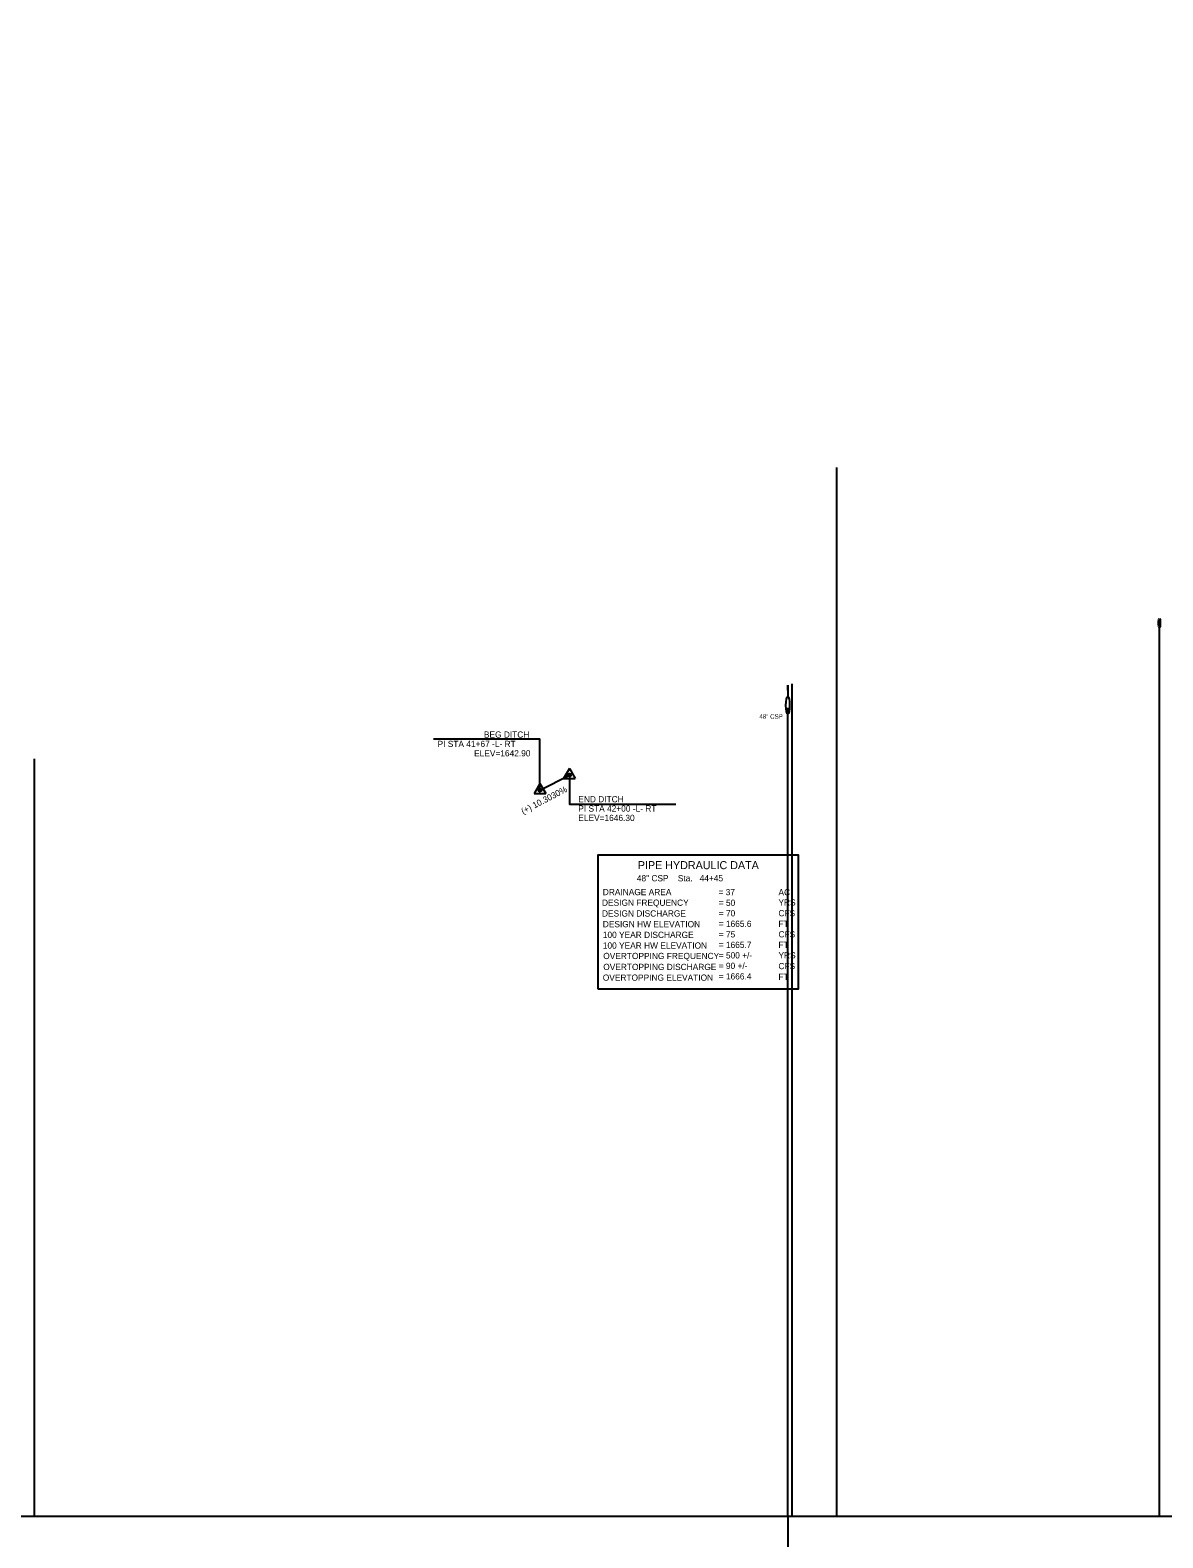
# Model space of a CAD drawing. Extents: x 1025306 to 1036906, y 638983 to 643947.
# Drawn here: x 1027901 to 1029171, y 639865 to 641557 of the extents above; entities that cross this region are included whole.
import ezdxf

# ---------------------------------------------------------------- set-up
doc = ezdxf.new("R2010")
doc.units = 0
for name, color, linetype in [('Default', 7, 'Continuous'), ('Prop PFL Cross Pipe CELL', 7, 'Continuous'), ('Prop PFL Cross Pipe Text CELL', 7, 'Continuous'), ('Prop PFL Pipe Hydraulic Data CELL', 7, 'Continuous'), ('Prop Vertical Profile Ditch Grade Right', 7, 'Continuous'), ('Prop Vertical Profile Ditch Grade Right Label', 7, 'Continuous'), ('Prop VPI Ditch Grade Right Label', 7, 'Continuous'), ('Scratch_Level_0', 7, 'Continuous'), ('Scratch_Level_1', 7, 'Continuous'), ('Scratch_Level_3', 7, 'Continuous')]:
    doc.layers.add(name, color=color, linetype=linetype)

msp = doc.modelspace()

# ---------------------------------------------------------------- linework, layer by layer
at = {"layer": 'Default'}
for p, q in [((1028505.6, 640728.4), (1028499.1, 640717.2)), ((1028505.6, 640728.4), (1028512.1, 640717.2)), ((1028472.6, 640711.4), (1028466.1, 640700.2)), ((1028472.6, 640711.4), (1028479.1, 640700.2)), ((1028499.1, 640717.2), (1028512.1, 640717.2)), ((1028466.1, 640700.2), (1028479.1, 640700.2))]:
    msp.add_line(p, q, dxfattribs=at)
for centre, radius in [((1028505.6, 640720.9), 1.75), ((1028505.6, 640720.9), 1.2), ((1028472.6, 640703.9), 1.75), ((1028472.6, 640703.9), 1.2)]:
    msp.add_circle(centre, radius, dxfattribs=at)
at = {"layer": 'Prop PFL Cross Pipe CELL'}
for centre, major_axis in [((1029167.6, 640891.4), (0, 5)), ((1028750.6, 640799.1), (0, 10))]:
    msp.add_ellipse(centre, major_axis=major_axis, ratio=0.2, dxfattribs=at)
at = {"layer": 'Prop PFL Pipe Hydraulic Data CELL'}
msp.add_lwpolyline([(1028537.6, 640481), (1028762.6, 640481), (1028762.6, 640631), (1028537.6, 640631)], close=True, dxfattribs=at)
at = {"layer": 'Prop Vertical Profile Ditch Grade Right'}
msp.add_line((1028472.6, 640703.9), (1028505.6, 640720.9), dxfattribs=at)
at = {"layer": 'Prop VPI Ditch Grade Right Label'}
for points in [[(1028472.6, 640703.9), (1028472.6, 640761.3), (1028353.1, 640761.3)], [(1028505.6, 640720.9), (1028505.6, 640688.4), (1028625.1, 640688.4)]]:
    msp.add_lwpolyline(points, dxfattribs=at)
for centre in [(1028505.6, 640720.9), (1028472.6, 640703.9)]:
    msp.add_circle(centre, 0.5, dxfattribs=at)
at = {"layer": 'Scratch_Level_0'}
for p, q in [((1028750.6, 640816.3), (1028750.6, 640821.6)), ((1028750.6, 640821.6), (1028750.6, 640809.1)), ((1028750.6, 639889.4), (1028750.6, 640796.3)), ((1025305.6, 639889.4), (1029505.6, 639889.4))]:
    msp.add_line(p, q, dxfattribs=at)
for points in [[(1025305.6, 639889.4), (1033905.6, 639889.4), (1033905.6, 643046.4)], [(1025305.6, 639889.4), (1033375.6, 639889.4), (1033375.6, 642934.5)], [(1025305.6, 639889.4), (1035605.6, 639889.4), (1035605.6, 642735.7)], [(1025305.6, 639889.4), (1035600.4, 639889.4), (1035600.4, 642734.5)], [(1025305.6, 639889.4), (1035578, 639889.4), (1035578, 642729)], [(1025305.6, 639889.4), (1035555.6, 639889.4), (1035555.6, 642723.6)], [(1025305.6, 639889.4), (1035514.6, 639889.4), (1035514.6, 642713.6)], [(1025305.6, 639889.4), (1035505.6, 639889.4), (1035505.6, 642711.4)], [(1025305.6, 639889.4), (1035455.6, 639889.4), (1035455.6, 642699.2)], [(1025305.6, 639889.4), (1035405.6, 639889.4), (1035405.6, 642687.9)], [(1025305.6, 639889.4), (1033855.6, 639889.4), (1033855.6, 642684.6)], [(1025305.6, 639889.4), (1034755.6, 639889.4), (1034755.6, 642682.7)], [(1025305.6, 639889.4), (1035205.6, 639889.4), (1035205.6, 642658.7)], [(1025305.6, 639889.4), (1035155.6, 639889.4), (1035155.6, 642655.4)], [(1025305.6, 639889.4), (1035105.6, 639889.4), (1035105.6, 642653.6)], [(1025305.6, 639889.4), (1035055.6, 639889.4), (1035055.6, 642653.4)], [(1025305.6, 639889.4), (1033655.6, 639889.4), (1033655.6, 642644)], [(1025305.6, 639889.4), (1032988.4, 639889.4), (1032988.4, 642410.8)], [(1025305.6, 639889.4), (1031301.6, 639889.4), (1031301.6, 641735.1)], [(1025305.6, 639889.4), (1029805.6, 639889.4), (1029805.6, 641516)], [(1025305.6, 639889.4), (1029655.6, 639889.4), (1029655.6, 641215.6)], [(1025305.6, 639889.4), (1029755.6, 639889.4), (1029755.6, 641210.8)], [(1025305.6, 639889.4), (1029705.6, 639889.4), (1029705.6, 641192.2)], [(1025305.6, 639889.4), (1029553.6, 639889.4), (1029553.6, 641131.2)], [(1025305.6, 639889.4), (1029505.6, 639889.4), (1029505.6, 641113.1)], [(1025305.6, 639889.4), (1029455.6, 639889.4), (1029455.6, 641093.2)], [(1025305.6, 639889.4), (1029405.6, 639889.4), (1029405.6, 641073.3)], [(1025305.6, 639889.4), (1028755.6, 639889.4), (1028755.6, 640823.4)], [(1025305.6, 639889.4), (1028750.6, 639889.4), (1028750.6, 638982.6)]]:
    msp.add_lwpolyline(points, dxfattribs=at)
at = {"layer": 'Scratch_Level_1'}
msp.add_line((1025305.6, 639889.4), (1032987.6, 639889.4), dxfattribs=at)
for points in [[(1025305.6, 639889.4), (1032987.6, 639889.4), (1032987.6, 642398)], [(1025305.6, 639889.4), (1032571.6, 639889.4), (1032571.6, 642222.1)], [(1025305.6, 639889.4), (1031338.6, 639889.4), (1031338.6, 641754.5)], [(1025305.6, 639889.4), (1031300.6, 639889.4), (1031300.6, 641742.5)], [(1025305.6, 639889.4), (1029167.6, 639889.4), (1029167.6, 640886.4)]]:
    msp.add_lwpolyline(points, dxfattribs=at)
at = {"layer": 'Scratch_Level_3'}
for p, q in [((1028805.6, 639889.4), (1028805.6, 641066.1)), ((1027905.6, 639889.4), (1027905.6, 640738.9))]:
    msp.add_line(p, q, dxfattribs=at)

# ---------------------------------------------------------------- texts
at = {"layer": 'Prop PFL Cross Pipe Text CELL'}
msp.add_text('48" CSP', height=5, dxfattribs=at).set_placement((1028718.8, 640784.1))
at = {"layer": 'Prop PFL Pipe Hydraulic Data CELL'}
for s, height, p in [('PIPE HYDRAULIC DATA', 9, (1028582.4, 640615.3)), ('  48" CSP    Sta.   44+45  ', 7, (1028576.1, 640601.6)), ('DRAINAGE AREA', 7, (1028543.1, 640586.1)), ('= 37  ', 7, (1028672.9, 640586.1)), ('AC', 7, (1028740.2, 640585.9)), ('DESIGN FREQUENCY', 7, (1028542.2, 640574.2)), ('= 50 ', 7, (1028673.2, 640574.1)), ('YRS', 7, (1028740.2, 640574.5)), ('CFS', 7, (1028740.2, 640562.4)), ('DESIGN DISCHARGE', 7, (1028542.2, 640562.1)), ('DESIGN HW ELEVATION', 7, (1028543.1, 640550.1)), ('= 70 ', 7, (1028673.2, 640562.3)), ('= 1665.6', 7, (1028673.2, 640550.5)), ('FT', 7, (1028740.2, 640550.5)), ('100 YEAR DISCHARGE', 7, (1028543.1, 640538.1)), ('= 75 ', 7, (1028673.2, 640538.7)), ('CFS', 7, (1028740.2, 640538.7)), ('100 YEAR HW ELEVATION', 7, (1028543.1, 640526.1)), ('OVERTOPPING FREQUENCY', 7, (1028543.6, 640514.4)), ('= 1665.7', 7, (1028673.2, 640526.9)), ('= 500 +/-', 7, (1028673.2, 640515.1)), ('YRS', 7, (1028740.2, 640515.2)), ('FT', 7, (1028740.2, 640526.9)), ('OVERTOPPING DISCHARGE', 7, (1028543.6, 640502.1)), ('= 90 +/-', 7, (1028673.2, 640503.3)), ('CFS', 7, (1028740.2, 640503.1)), ('OVERTOPPING ELEVATION', 7, (1028543.1, 640490.1)), ('= 1666.4', 7, (1028673.2, 640491.5)), ('FT', 7, (1028740.2, 640491.1))]:
    msp.add_text(s, height=height, dxfattribs=at).set_placement(p)
at = {"layer": 'Prop Vertical Profile Ditch Grade Right Label'}
msp.add_text('(+) 10.3030%', height=7, rotation=27.2553, dxfattribs=at).set_placement((1028453.7, 640676.7))
at = {"layer": 'Prop VPI Ditch Grade Right Label'}
for s, p in [('PI STA 41+67 -L- RT', (1028357.7, 640752.3)), ('BEG DITCH', (1028409.7, 640762.8)), ('ELEV=1642.90', (1028398.7, 640741.8)), ('END DITCH', (1028515.6, 640690.3)), ('PI STA 42+00 -L- RT', (1028515.6, 640679.8)), ('ELEV=1646.30', (1028515.6, 640669.3))]:
    msp.add_text(s, height=7, dxfattribs=at).set_placement(p)

doc.saveas('drawing.dxf')
